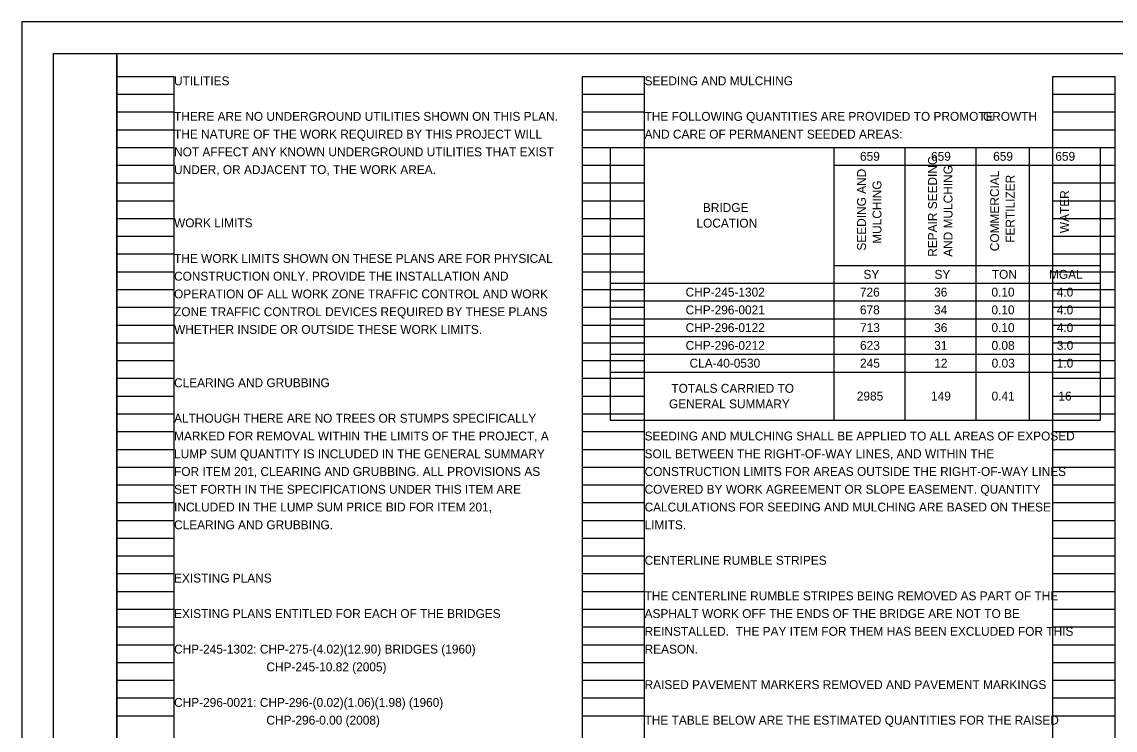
# Model space of a CAD drawing. Extents: x -49 to 78, y -12 to 34.
# Drawn here: x 0 to 17.24, y 10.83 to 22 of the extents above; entities that cross this region are included whole.
import ezdxf

# ---------------------------------------------------------------- set-up
doc = ezdxf.new("R2010")
doc.units = 0
for name, color, linetype in [('SC_Scratch1', 7, 'Continuous'), ('SH_Border', 7, 'Continuous'), ('SH_Cut_Line', 7, 'Continuous'), ('SH_Data', 7, 'Continuous'), ('SH_Text', 7, 'Continuous')]:
    doc.layers.add(name, color=color, linetype=linetype)

msp = doc.modelspace()

# ---------------------------------------------------------------- linework, layer by layer
at = {"layer": 'SC_Scratch1'}
for p, q in [((1.5, 0.98), (1.5, 21.14)), ((1.5, 21.14), (2.4, 21.14)), ((2.4, 0.98), (2.4, 21.14)), ((8.84, 0.98), (8.84, 21.14)), ((8.84, 21.14), (9.82, 21.14)), ((9.82, 0.98), (9.82, 21.14)), ((16.26, 0.98), (16.26, 21.14)), ((16.26, 21.14), (17.24, 21.14)), ((17.24, 0.98), (17.24, 21.14)), ((1.5, 20.86), (2.4, 20.86)), ((8.84, 20.86), (9.82, 20.86)), ((16.26, 20.86), (17.24, 20.86)), ((1.5, 20.58), (2.4, 20.58)), ((8.84, 20.58), (9.82, 20.58)), ((16.26, 20.58), (17.24, 20.58)), ((1.5, 20.3), (2.4, 20.3)), ((8.84, 20.3), (9.82, 20.3)), ((16.26, 20.3), (17.24, 20.3)), ((1.5, 20.02), (2.4, 20.02)), ((8.84, 20.02), (9.82, 20.02)), ((16.26, 20.02), (17.24, 20.02)), ((1.5, 19.74), (2.4, 19.74)), ((8.84, 19.74), (9.82, 19.74)), ((16.26, 19.74), (17.24, 19.74)), ((1.5, 19.46), (2.4, 19.46)), ((8.84, 19.46), (9.82, 19.46)), ((16.26, 19.46), (17.24, 19.46)), ((1.5, 19.18), (2.4, 19.18)), ((8.84, 19.18), (9.82, 19.18)), ((16.26, 19.18), (17.24, 19.18)), ((1.5, 18.9), (2.4, 18.9)), ((8.84, 18.9), (9.82, 18.9)), ((16.26, 18.9), (17.24, 18.9)), ((1.5, 18.62), (2.4, 18.62)), ((8.84, 18.62), (9.82, 18.62)), ((16.26, 18.62), (17.24, 18.62)), ((1.5, 18.34), (2.4, 18.34)), ((8.84, 18.34), (9.82, 18.34)), ((16.26, 18.34), (17.24, 18.34)), ((1.5, 18.06), (2.4, 18.06)), ((8.84, 18.06), (9.82, 18.06)), ((16.26, 18.06), (17.24, 18.06)), ((1.5, 17.78), (2.4, 17.78)), ((8.84, 17.78), (9.82, 17.78)), ((16.26, 17.78), (17.24, 17.78)), ((1.5, 17.5), (2.4, 17.5)), ((8.84, 17.5), (9.82, 17.5)), ((16.26, 17.5), (17.24, 17.5)), ((1.5, 17.22), (2.4, 17.22)), ((8.84, 17.22), (9.82, 17.22)), ((16.26, 17.22), (17.24, 17.22)), ((1.5, 16.94), (2.4, 16.94)), ((8.84, 16.94), (9.82, 16.94)), ((16.26, 16.94), (17.24, 16.94)), ((1.5, 16.66), (2.4, 16.66)), ((8.84, 16.66), (9.82, 16.66)), ((16.26, 16.66), (17.24, 16.66)), ((1.5, 16.38), (2.4, 16.38)), ((8.84, 16.38), (9.82, 16.38)), ((16.26, 16.38), (17.24, 16.38)), ((1.5, 16.1), (2.4, 16.1)), ((8.84, 16.1), (9.82, 16.1)), ((16.26, 16.1), (17.24, 16.1)), ((1.5, 15.82), (2.4, 15.82)), ((8.84, 15.82), (9.82, 15.82)), ((16.26, 15.82), (17.24, 15.82)), ((1.5, 15.54), (2.4, 15.54)), ((8.84, 15.54), (9.82, 15.54)), ((16.26, 15.54), (17.24, 15.54)), ((1.5, 15.26), (2.4, 15.26)), ((8.84, 15.26), (9.82, 15.26)), ((16.26, 15.26), (17.24, 15.26)), ((1.5, 14.98), (2.4, 14.98)), ((8.84, 14.98), (9.82, 14.98)), ((16.26, 14.98), (17.24, 14.98)), ((1.5, 14.7), (2.4, 14.7)), ((8.84, 14.7), (9.82, 14.7)), ((16.26, 14.7), (17.24, 14.7)), ((1.5, 14.42), (2.4, 14.42)), ((8.84, 14.42), (9.82, 14.42)), ((16.26, 14.42), (17.24, 14.42)), ((1.5, 14.14), (2.4, 14.14)), ((8.84, 14.14), (9.82, 14.14)), ((16.26, 14.14), (17.24, 14.14)), ((1.5, 13.86), (2.4, 13.86)), ((8.84, 13.86), (9.82, 13.86)), ((16.26, 13.86), (17.24, 13.86)), ((1.5, 13.58), (2.4, 13.58)), ((8.84, 13.58), (9.82, 13.58)), ((16.26, 13.58), (17.24, 13.58)), ((1.5, 13.3), (2.4, 13.3)), ((8.84, 13.3), (9.82, 13.3)), ((16.26, 13.3), (17.24, 13.3)), ((1.5, 13.02), (2.4, 13.02)), ((8.84, 13.02), (9.82, 13.02)), ((16.26, 13.02), (17.24, 13.02)), ((1.5, 12.74), (2.4, 12.74)), ((8.84, 12.74), (9.82, 12.74)), ((16.26, 12.74), (17.24, 12.74)), ((1.5, 12.46), (2.4, 12.46)), ((8.84, 12.46), (9.82, 12.46)), ((16.26, 12.46), (17.24, 12.46)), ((1.5, 12.18), (2.4, 12.18)), ((8.84, 12.18), (9.82, 12.18)), ((16.26, 12.18), (17.24, 12.18)), ((1.5, 11.9), (2.4, 11.9)), ((8.84, 11.9), (9.82, 11.9)), ((16.26, 11.9), (17.24, 11.9)), ((1.5, 11.62), (2.4, 11.62)), ((8.84, 11.62), (9.82, 11.62)), ((16.26, 11.62), (17.24, 11.62)), ((1.5, 11.34), (2.4, 11.34)), ((8.84, 11.34), (9.82, 11.34)), ((16.26, 11.34), (17.24, 11.34)), ((1.5, 11.06), (2.4, 11.06)), ((8.84, 11.06), (9.82, 11.06)), ((16.26, 11.06), (17.24, 11.06))]:
    msp.add_line(p, q, dxfattribs=at)
at = {"layer": 'SH_Border'}
for points in [[(0.5, 21.5), (1.5, 21.5), (1.5, 0.5), (0.5, 0.5)], [(1.5, 21.5), (33.5, 21.5), (33.5, 0.5), (1.5, 0.5)]]:
    msp.add_lwpolyline(points, close=True, dxfattribs=at)
at = {"layer": 'SH_Cut_Line'}
msp.add_lwpolyline([(0, 0), (34, 0), (34, 22), (0, 22)], close=True, dxfattribs=at)
at = {"layer": 'SH_Data'}
for p, q in [((9.278, 20.02), (17.003, 20.02)), ((9.278, 20.02), (9.278, 15.721)), ((12.803, 20.02), (12.803, 15.721)), ((13.923, 20.02), (13.923, 15.721)), ((15.043, 20.02), (15.043, 15.721)), ((15.883, 20.02), (15.883, 15.721)), ((17.003, 20.02), (17.003, 15.721)), ((12.803, 19.74), (17.003, 19.74)), ((12.803, 18.159), (17.003, 18.159)), ((9.278, 17.879), (17.003, 17.879)), ((9.278, 17.599), (17.003, 17.599)), ((9.278, 17.319), (17.003, 17.319)), ((9.278, 17.039), (17.003, 17.039)), ((9.278, 16.759), (17.003, 16.759)), ((9.278, 16.479), (17.003, 16.479)), ((9.278, 15.721), (17.003, 15.721))]:
    msp.add_line(p, q, dxfattribs=at)

# ---------------------------------------------------------------- texts
at = {"layer": 'SH_Text'}
for s, p in [('UTILITIES', (2.4, 21)), ('SEEDING AND MULCHING', (9.82, 21)), ('THERE ARE NO UNDERGROUND UTILITIES SHOWN ON THIS PLAN. ', (2.4, 20.44)), ('THE FOLLOWING QUANTITIES ARE PROVIDED TO PROMOTE ', (9.82, 20.44)), ('GROWTH ', (15.156, 20.44)), ('THE NATURE OF THE WORK REQUIRED BY THIS PROJECT WILL ', (2.4, 20.16)), ('AND CARE OF PERMANENT SEEDED AREAS:', (9.82, 20.16)), ('NOT AFFECT ANY KNOWN UNDERGROUND UTILITIES THAT EXIST ', (2.4, 19.88)), ('659', (13.217, 19.81)), ('659', (14.337, 19.81)), ('659', (15.317, 19.81)), ('659', (16.297, 19.81)), ('UNDER, OR ADJACENT TO, THE WORK AREA.', (2.4, 19.6)), ('BRIDGE ', (10.74, 19.002)), ('WORK LIMITS', (2.4, 18.76)), ('LOCATION', (10.638, 18.757)), ('THE WORK LIMITS SHOWN ON THESE PLANS ARE FOR PHYSICAL ', (2.4, 18.2)), ('CONSTRUCTION ONLY. PROVIDE THE INSTALLATION AND ', (2.4, 17.92)), ('SY', (13.271, 17.949)), ('SY', (14.391, 17.949)), ('TON', (15.296, 17.949)), ('MGAL', (16.197, 17.949)), ('OPERATION OF ALL WORK ZONE TRAFFIC CONTROL AND WORK ', (2.4, 17.64)), ('CHP-245-1302', (10.467, 17.669)), ('726', (13.216, 17.669)), ('36', (14.386, 17.669)), ('0.10', (15.29, 17.669)), ('4.0', (16.32, 17.669)), ('ZONE TRAFFIC CONTROL DEVICES REQUIRED BY THESE PLANS ', (2.4, 17.36)), ('CHP-296-0021', (10.467, 17.389)), ('678', (13.216, 17.389)), ('34', (14.385, 17.389)), ('0.10', (15.29, 17.389)), ('4.0', (16.32, 17.389)), ('CHP-296-0122', (10.467, 17.109)), ('713', (13.218, 17.109)), ('36', (14.386, 17.109)), ('0.10', (15.29, 17.109)), ('4.0', (16.32, 17.109)), ('WHETHER INSIDE OR OUTSIDE THESE WORK LIMITS.', (2.4, 17.08)), ('CHP-296-0212', (10.467, 16.829)), ('623', (13.218, 16.829)), ('31', (14.387, 16.829)), ('0.08', (15.291, 16.829)), ('3.0', (16.32, 16.829)), ('CLA-40-0530', (10.529, 16.549)), ('245', (13.218, 16.549)), ('12', (14.388, 16.549)), ('0.03', (15.293, 16.549)), ('1.0', (16.32, 16.549)), ('CLEARING AND GRUBBING', (2.4, 16.24)), ('TOTALS CARRIED TO', (10.242, 16.152)), ('GENERAL SUMMARY', (10.205, 15.907)), ('2985', (13.167, 16.03)), ('149', (14.337, 16.03)), ('0.41', (15.292, 16.03)), ('16', (16.346, 16.03)), ('ALTHOUGH THERE ARE NO TREES OR STUMPS SPECIFICALLY ', (2.4, 15.68)), ('MARKED FOR REMOVAL WITHIN THE LIMITS OF THE PROJECT, A ', (2.4, 15.4)), ('SEEDING AND MULCHING SHALL BE APPLIED TO ALL AREAS OF EXPOSED ', (9.82, 15.4)), ('LUMP SUM QUANTITY IS INCLUDED IN THE GENERAL SUMMARY ', (2.4, 15.12)), ('SOIL BETWEEN THE RIGHT-OF-WAY LINES, AND WITHIN THE ', (9.82, 15.12)), ('FOR ITEM 201, CLEARING AND GRUBBING. ALL PROVISIONS AS ', (2.4, 14.84)), ('CONSTRUCTION LIMITS FOR AREAS OUTSIDE THE RIGHT-OF-WAY LINES ', (9.82, 14.84)), ('SET FORTH IN THE SPECIFICATIONS UNDER THIS ITEM ARE ', (2.4, 14.56)), ('COVERED BY WORK AGREEMENT OR SLOPE EASEMENT. QUANTITY ', (9.82, 14.56)), ('INCLUDED IN THE LUMP SUM PRICE BID FOR ITEM 201, ', (2.4, 14.28)), ('CALCULATIONS FOR SEEDING AND MULCHING ARE BASED ON THESE ', (9.82, 14.28)), ('CLEARING AND GRUBBING.', (2.4, 14)), ('LIMITS.', (9.82, 14)), ('CENTERLINE RUMBLE STRIPES', (9.82, 13.44)), ('EXISTING PLANS', (2.4, 13.16)), ('THE CENTERLINE RUMBLE STRIPES BEING REMOVED AS PART OF THE ', (9.82, 12.88)), ('EXISTING PLANS ENTITLED FOR EACH OF THE BRIDGES', (2.4, 12.6)), ('ASPHALT WORK OFF THE ENDS OF THE BRIDGE ARE NOT TO BE ', (9.82, 12.6)), ('REINSTALLED.  THE PAY ITEM FOR THEM HAS BEEN EXCLUDED FOR THIS ', (9.82, 12.32)), ('CHP-245-1302: CHP-275-(4.02)(12.90) BRIDGES (1960)', (2.4, 12.04)), ('REASON.', (9.82, 12.04)), ('                            CHP-245-10.82 (2005)', (2.4, 11.76)), ('RAISED PAVEMENT MARKERS REMOVED AND PAVEMENT MARKINGS', (9.82, 11.48)), ('CHP-296-0021: CHP-296-(0.02)(1.06)(1.98) (1960)', (2.4, 11.2)), ('                            CHP-296-0.00 (2008)', (2.4, 10.92)), ('THE TABLE BELOW ARE THE ESTIMATED QUANTITIES FOR THE RAISED ', (9.82, 10.92))]:
    msp.add_text(s, height=0.14, dxfattribs=at).set_placement(p)
for s, p in [('REPAIR SEEDING ', (14.43, 18.296)), ('SEEDING AND ', (13.31, 18.394)), ('AND MULCHING', (14.675, 18.296)), ('MULCHING', (13.555, 18.501)), ('COMMERCIAL ', (15.41, 18.384)), ('FERTILIZER', (15.655, 18.517)), ('WATER', (16.513, 18.669))]:
    msp.add_text(s, height=0.14, rotation=90, dxfattribs=at).set_placement(p)

doc.saveas('drawing.dxf')
